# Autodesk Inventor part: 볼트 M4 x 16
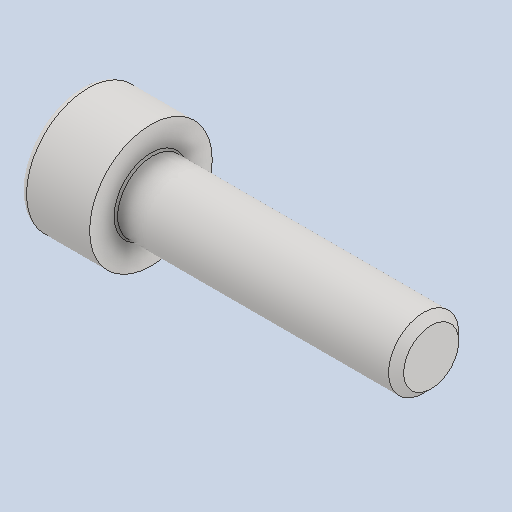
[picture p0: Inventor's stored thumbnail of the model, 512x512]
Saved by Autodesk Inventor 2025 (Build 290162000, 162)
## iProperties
Created: 2024-07
Part Number: 볼트 M4 x 16
Material: 스테인리스강
Description: 6각 소켓 머리 캡 나사
Document SubType Name: Modeling
Designer: deana
Density: 8.08 g/cm^3
Appearance: 기본값
Author: jhkim
Sending System: Autodesk Inventor 2025
Preprocessor: ST-DEVELOPER v20
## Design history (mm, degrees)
feature "Solid1"
node "솔리드1"
